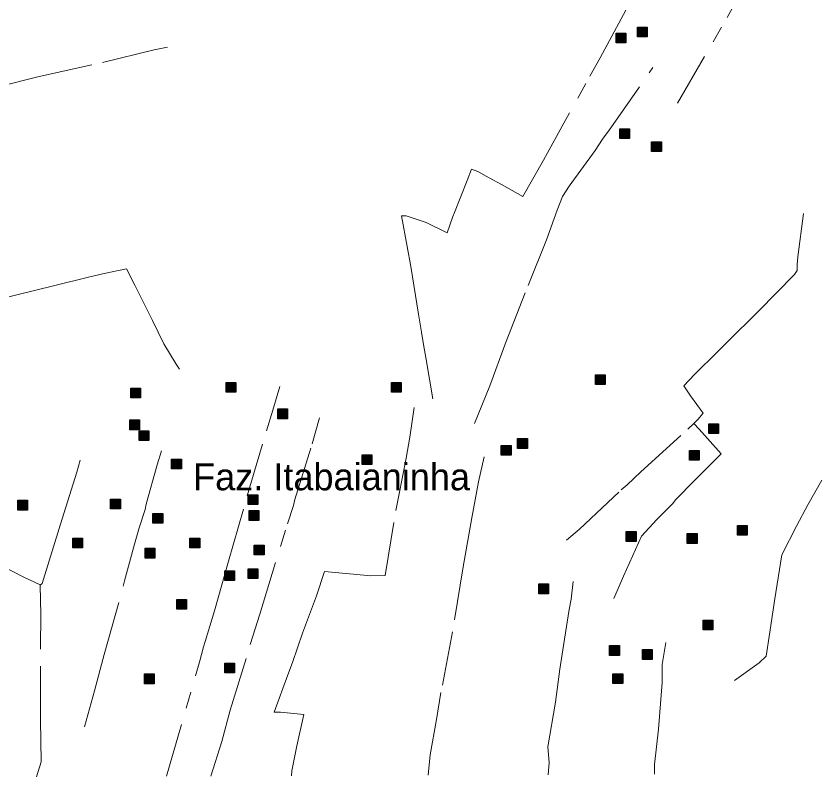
# Model space of a CAD drawing. Extents: x 393.5 to 446.9, y 8064.8 to 8120.4.
# Drawn here: x 413.443 to 418.221, y 8064.925 to 8069.434 of the extents above; entities that cross this region are included whole.
import ezdxf

# ---------------------------------------------------------------- set-up
doc = ezdxf.new("R2010")
doc.units = 0
doc.header["$LTSCALE"] = 0.064
doc.linetypes.add('DOT_DASHED', pattern=[7.7, 5, -1.2, 0.3, -1.2])
doc.layers.add('2', color=7, linetype='Continuous', lineweight=25)
doc.layers.add('22', color=7, linetype='DOT_DASHED', lineweight=13)
doc.layers.add('61', color=7, linetype='Continuous')

msp = doc.modelspace()

# ---------------------------------------------------------------- hatches: boundary and pattern name
at = {"layer": '2'}
for points in [[(417.1265, 8069.3684), (417.1845, 8069.3684), (417.1845, 8069.3104), (417.1265, 8069.3104)], [(417.0004, 8069.3332), (417.0584, 8069.3332), (417.0584, 8069.2752), (417.0004, 8069.2752)], [(417.0219, 8068.7657), (417.0799, 8068.7657), (417.0799, 8068.7077), (417.0219, 8068.7077)], [(417.2112, 8068.689), (417.2692, 8068.689), (417.2692, 8068.631), (417.2112, 8068.631)], [(416.8775, 8067.3086), (416.9355, 8067.3086), (416.9355, 8067.2506), (416.8775, 8067.2506)], [(414.688, 8067.2634), (414.746, 8067.2634), (414.746, 8067.2054), (414.688, 8067.2054)], [(415.6682, 8067.2634), (415.7262, 8067.2634), (415.7262, 8067.2054), (415.6682, 8067.2054)], [(414.1226, 8067.229), (414.1806, 8067.229), (414.1806, 8067.171), (414.1226, 8067.171)], [(414.9945, 8067.1054), (415.0525, 8067.1054), (415.0525, 8067.0474), (414.9945, 8067.0474)], [(414.1167, 8067.0407), (414.1747, 8067.0407), (414.1747, 8066.9827), (414.1167, 8066.9827)], [(417.5499, 8067.0181), (417.6079, 8067.0181), (417.6079, 8066.9601), (417.5499, 8066.9601)], [(414.173, 8066.9761), (414.231, 8066.9761), (414.231, 8066.9181), (414.173, 8066.9181)], [(416.4165, 8066.9296), (416.4745, 8066.9296), (416.4745, 8066.8716), (416.4165, 8066.8716)], [(416.3201, 8066.8889), (416.3781, 8066.8889), (416.3781, 8066.8309), (416.3201, 8066.8309)], [(417.4348, 8066.8598), (417.4928, 8066.8598), (417.4928, 8066.8018), (417.4348, 8066.8018)], [(415.4943, 8066.8342), (415.5523, 8066.8342), (415.5523, 8066.7762), (415.4943, 8066.7762)], [(414.3649, 8066.8086), (414.4229, 8066.8086), (414.4229, 8066.7506), (414.3649, 8066.7506)], [(414.0032, 8066.5708), (414.0612, 8066.5708), (414.0612, 8066.5128), (414.0032, 8066.5128)], [(414.8188, 8066.5967), (414.8768, 8066.5967), (414.8768, 8066.5387), (414.8188, 8066.5387)], [(413.4528, 8066.5648), (413.5108, 8066.5648), (413.5108, 8066.5068), (413.4528, 8066.5068)], [(414.2547, 8066.4869), (414.3127, 8066.4869), (414.3127, 8066.4289), (414.2547, 8066.4289)], [(414.8249, 8066.5031), (414.8829, 8066.5031), (414.8829, 8066.4451), (414.8249, 8066.4451)], [(417.0611, 8066.3789), (417.1191, 8066.3789), (417.1191, 8066.3209), (417.0611, 8066.3209)], [(417.7198, 8066.4158), (417.7778, 8066.4158), (417.7778, 8066.3578), (417.7198, 8066.3578)], [(413.7796, 8066.3397), (413.8376, 8066.3397), (413.8376, 8066.2817), (413.7796, 8066.2817)], [(414.4736, 8066.34), (414.5316, 8066.34), (414.5316, 8066.282), (414.4736, 8066.282)], [(417.4227, 8066.3671), (417.4807, 8066.3671), (417.4807, 8066.3091), (417.4227, 8066.3091)], [(414.8553, 8066.2988), (414.9133, 8066.2988), (414.9133, 8066.2408), (414.8553, 8066.2408)], [(414.2079, 8066.2797), (414.2659, 8066.2797), (414.2659, 8066.2217), (414.2079, 8066.2217)], [(414.6799, 8066.1467), (414.7379, 8066.1467), (414.7379, 8066.0887), (414.6799, 8066.0887)], [(414.8191, 8066.159), (414.8771, 8066.159), (414.8771, 8066.101), (414.8191, 8066.101)], [(416.5422, 8066.0685), (416.6002, 8066.0685), (416.6002, 8066.0105), (416.5422, 8066.0105)], [(414.3957, 8065.9764), (414.4537, 8065.9764), (414.4537, 8065.9184), (414.3957, 8065.9184)], [(417.5171, 8065.8543), (417.5751, 8065.8543), (417.5751, 8065.7963), (417.5171, 8065.7963)], [(416.9624, 8065.7034), (417.0204, 8065.7034), (417.0204, 8065.6454), (416.9624, 8065.6454)], [(417.1562, 8065.6792), (417.2142, 8065.6792), (417.2142, 8065.6212), (417.1562, 8065.6212)], [(414.6803, 8065.5992), (414.7383, 8065.5992), (414.7383, 8065.5412), (414.6803, 8065.5412)], [(414.2039, 8065.535), (414.2619, 8065.535), (414.2619, 8065.477), (414.2039, 8065.477)], [(416.9816, 8065.5358), (417.0396, 8065.5358), (417.0396, 8065.4778), (416.9816, 8065.4778)]]:
    msp.add_hatch(color=256, dxfattribs=at).paths.add_polyline_path(points)

# ---------------------------------------------------------------- linework, layer by layer
for points in [[(417.1265, 8069.3684), (417.1845, 8069.3684), (417.1845, 8069.3104), (417.1265, 8069.3104)], [(417.0004, 8069.3332), (417.0584, 8069.3332), (417.0584, 8069.2752), (417.0004, 8069.2752)], [(417.0219, 8068.7657), (417.0799, 8068.7657), (417.0799, 8068.7077), (417.0219, 8068.7077)], [(417.2112, 8068.689), (417.2692, 8068.689), (417.2692, 8068.631), (417.2112, 8068.631)], [(416.8775, 8067.3086), (416.9355, 8067.3086), (416.9355, 8067.2506), (416.8775, 8067.2506)], [(414.688, 8067.2634), (414.746, 8067.2634), (414.746, 8067.2054), (414.688, 8067.2054)], [(415.6682, 8067.2634), (415.7262, 8067.2634), (415.7262, 8067.2054), (415.6682, 8067.2054)], [(414.1226, 8067.229), (414.1806, 8067.229), (414.1806, 8067.171), (414.1226, 8067.171)], [(414.9945, 8067.1054), (415.0525, 8067.1054), (415.0525, 8067.0474), (414.9945, 8067.0474)], [(414.1167, 8067.0407), (414.1747, 8067.0407), (414.1747, 8066.9827), (414.1167, 8066.9827)], [(417.5499, 8067.0181), (417.6079, 8067.0181), (417.6079, 8066.9601), (417.5499, 8066.9601)], [(414.173, 8066.9761), (414.231, 8066.9761), (414.231, 8066.9181), (414.173, 8066.9181)], [(416.4165, 8066.9296), (416.4745, 8066.9296), (416.4745, 8066.8716), (416.4165, 8066.8716)], [(416.3201, 8066.8889), (416.3781, 8066.8889), (416.3781, 8066.8309), (416.3201, 8066.8309)], [(417.4348, 8066.8598), (417.4928, 8066.8598), (417.4928, 8066.8018), (417.4348, 8066.8018)], [(415.4943, 8066.8342), (415.5523, 8066.8342), (415.5523, 8066.7762), (415.4943, 8066.7762)], [(414.3649, 8066.8086), (414.4229, 8066.8086), (414.4229, 8066.7506), (414.3649, 8066.7506)], [(414.0032, 8066.5708), (414.0612, 8066.5708), (414.0612, 8066.5128), (414.0032, 8066.5128)], [(414.8188, 8066.5967), (414.8768, 8066.5967), (414.8768, 8066.5387), (414.8188, 8066.5387)], [(413.4528, 8066.5648), (413.5108, 8066.5648), (413.5108, 8066.5068), (413.4528, 8066.5068)], [(414.2547, 8066.4869), (414.3127, 8066.4869), (414.3127, 8066.4289), (414.2547, 8066.4289)], [(414.8249, 8066.5031), (414.8829, 8066.5031), (414.8829, 8066.4451), (414.8249, 8066.4451)], [(417.0611, 8066.3789), (417.1191, 8066.3789), (417.1191, 8066.3209), (417.0611, 8066.3209)], [(417.7198, 8066.4158), (417.7778, 8066.4158), (417.7778, 8066.3578), (417.7198, 8066.3578)], [(413.7796, 8066.3397), (413.8376, 8066.3397), (413.8376, 8066.2817), (413.7796, 8066.2817)], [(414.4736, 8066.34), (414.5316, 8066.34), (414.5316, 8066.282), (414.4736, 8066.282)], [(417.4227, 8066.3671), (417.4807, 8066.3671), (417.4807, 8066.3091), (417.4227, 8066.3091)], [(414.8553, 8066.2988), (414.9133, 8066.2988), (414.9133, 8066.2408), (414.8553, 8066.2408)], [(414.2079, 8066.2797), (414.2659, 8066.2797), (414.2659, 8066.2217), (414.2079, 8066.2217)], [(414.6799, 8066.1467), (414.7379, 8066.1467), (414.7379, 8066.0887), (414.6799, 8066.0887)], [(414.8191, 8066.159), (414.8771, 8066.159), (414.8771, 8066.101), (414.8191, 8066.101)], [(416.5422, 8066.0685), (416.6002, 8066.0685), (416.6002, 8066.0105), (416.5422, 8066.0105)], [(414.3957, 8065.9764), (414.4537, 8065.9764), (414.4537, 8065.9184), (414.3957, 8065.9184)], [(417.5171, 8065.8543), (417.5751, 8065.8543), (417.5751, 8065.7963), (417.5171, 8065.7963)], [(416.9624, 8065.7034), (417.0204, 8065.7034), (417.0204, 8065.6454), (416.9624, 8065.6454)], [(417.1562, 8065.6792), (417.2142, 8065.6792), (417.2142, 8065.6212), (417.1562, 8065.6212)], [(414.6803, 8065.5992), (414.7383, 8065.5992), (414.7383, 8065.5412), (414.6803, 8065.5412)], [(414.2039, 8065.535), (414.2619, 8065.535), (414.2619, 8065.477), (414.2039, 8065.477)], [(416.9816, 8065.5358), (417.0396, 8065.5358), (417.0396, 8065.4778), (416.9816, 8065.4778)]]:
    msp.add_lwpolyline(points, close=True, dxfattribs=at)
at = {"layer": '22'}
msp.add_line((413.5866, 8066.0621), (413.586, 8066.0624), dxfattribs=at)
for points in [[(416.3205, 8068.4365), (416.4474, 8068.3655), (416.5706, 8068.5796), (416.8448, 8069.0771), (416.9065, 8069.1873), (417.0942, 8069.5336), (417.1147, 8069.571), (417.1305, 8069.5899)], [(417.3653, 8068.9177), (417.6589, 8069.4259), (417.6985, 8069.4962), (417.7, 8069.4988)], [(412.4913, 8068.8155), (412.6773, 8068.8613), (412.8028, 8068.8883), (412.9867, 8068.934), (413.2711, 8068.9984), (413.5805, 8069.0753), (413.9559, 8069.1589), (414.2612, 8069.2336), (414.3406, 8069.2502)], [(416.9481, 8068.7428), (416.9549, 8068.7526), (417.2182, 8069.1284)], [(416.1609, 8067.019), (416.2529, 8067.2418), (416.345, 8067.4952), (416.4799, 8067.8378), (416.5885, 8068.1084), (416.6518, 8068.284), (416.6827, 8068.3647), (416.7223, 8068.4251), (416.8766, 8068.6377), (416.9204, 8068.7044), (416.9481, 8068.7428)], [(416.0424, 8068.27), (416.1177, 8068.4604), (416.1441, 8068.5269), (416.1815, 8068.512), (416.2488, 8068.4746), (416.3205, 8068.4365)], [(415.7621, 8068.0687), (415.7276, 8068.2497), (415.7557, 8068.2497), (415.8735, 8068.2104), (415.9988, 8068.1488), (416.0324, 8068.2459), (416.0424, 8068.27)], [(418.0736, 8067.9624), (418.079, 8068.0077), (418.1109, 8068.2648)], [(415.8476, 8067.5613), (415.8296, 8067.6676), (415.7837, 8067.9507), (415.7621, 8068.0687)], [(417.4612, 8067.019), (417.4855, 8067.044), (417.5159, 8067.0807), (417.4424, 8067.1829), (417.4024, 8067.2419), (417.4647, 8067.3106), (417.602, 8067.4438), (417.658, 8067.4997), (417.8449, 8067.6848), (418.0589, 8067.9032), (418.0736, 8067.9262), (418.0736, 8067.9451), (418.0736, 8067.9624)], [(414.4117, 8067.3405), (414.3916, 8067.3716), (414.3182, 8067.4925), (414.252, 8067.6303), (414.1464, 8067.8398), (414.0977, 8067.9358), (413.9652, 8067.9088), (413.8716, 8067.8862)], [(413.8716, 8067.8862), (413.6733, 8067.8377), (413.4388, 8067.7794), (412.9923, 8067.6724), (412.9237, 8067.6565), (412.922, 8067.6561)], [(415.9145, 8067.1655), (415.8753, 8067.3991), (415.8584, 8067.4869), (415.8476, 8067.5613)], [(414.5648, 8065.7271), (414.6191, 8065.9096), (414.702, 8066.2036), (414.8135, 8066.5905), (414.9279, 8066.9765), (414.9661, 8067.098), (415.0065, 8067.2381)], [(415.7567, 8066.8142), (415.777, 8066.9379), (415.803, 8067.1142)], [(415.0961, 8066.5683), (415.1992, 8066.8988), (415.2428, 8067.0533)], [(417.0668, 8066.6562), (417.1468, 8066.734), (417.4262, 8066.9855), (417.4612, 8067.019)], [(417.3553, 8066.5698), (417.4648, 8066.6807), (417.6226, 8066.8402), (417.4932, 8066.9854), (417.4614, 8067.0188), (417.4612, 8067.019)], [(414.2149, 8066.542), (414.2791, 8066.7745), (414.3049, 8066.8581)], [(415.0816, 8065.6031), (415.1417, 8065.7774), (415.2246, 8065.9975), (415.2718, 8066.1427), (415.5457, 8066.1158), (415.631, 8066.1181), (415.6954, 8066.5043), (415.7117, 8066.5935), (415.7567, 8066.8142)], [(416.2176, 8066.8223), (416.1844, 8066.6742), (416.1455, 8066.4612), (416.0935, 8066.171), (416.0305, 8065.7841), (415.962, 8065.4247), (415.9361, 8065.2653), (415.8976, 8065.0554), (415.8855, 8064.935)], [(413.8237, 8066.802), (413.8026, 8066.7316), (413.7165, 8066.4542), (413.6461, 8066.2309), (413.597, 8066.0722), (413.5866, 8066.0621)], [(417.7031, 8065.4971), (417.8491, 8065.6007), (417.8896, 8065.6413), (417.9119, 8065.7834), (417.9404, 8065.9682), (417.9834, 8066.2417), (418.0727, 8066.4142), (418.1376, 8066.5382), (418.2207, 8066.6827)], [(416.7068, 8066.328), (416.7831, 8066.3935), (417.0305, 8066.627), (417.0668, 8066.6562)], [(413.8487, 8065.2209), (413.9078, 8065.435), (413.9662, 8065.6506), (414.0867, 8066.0874), (414.1442, 8066.3041), (414.1724, 8066.4003), (414.2079, 8066.5098), (414.2149, 8066.542)], [(414.5968, 8064.9297), (414.6635, 8065.1349), (414.7128, 8065.3215), (414.8314, 8065.7096), (414.8874, 8065.8893), (415.0519, 8066.4248), (415.0877, 8066.5344), (415.0961, 8066.5683)], [(416.9872, 8065.9832), (417.0453, 8066.1148), (417.1504, 8066.3514), (417.243, 8066.4504), (417.3341, 8066.543), (417.3553, 8066.5698)], [(413.586, 8066.0624), (413.4894, 8066.108), (413.3441, 8066.1815), (413.3249, 8066.2037), (413.2597, 8066.3487), (413.2265, 8066.4217), (413.1904, 8066.4942), (413.183, 8066.512)], [(413.5901, 8065.8634), (413.5901, 8065.886), (413.5866, 8066.0606), (413.5866, 8066.0621)], [(416.7453, 8066.083), (416.7343, 8065.9776), (416.7214, 8065.9167), (416.6955, 8065.7422), (416.6679, 8065.5637), (416.6421, 8065.3678), (416.5953, 8065.1042), (416.6034, 8065.0109), (416.5973, 8064.938)], [(413.5645, 8064.9253), (413.5909, 8065.0148), (413.5872, 8065.2618), (413.5881, 8065.7154), (413.5901, 8065.8634)], [(414.3345, 8064.9286), (414.532, 8065.6121), (414.5416, 8065.6503), (414.5545, 8065.6967), (414.5648, 8065.7271)], [(417.2279, 8064.9406), (417.2279, 8064.9987), (417.2522, 8065.2083), (417.2746, 8065.4848), (417.2746, 8065.5903), (417.2949, 8065.7221)], [(415.0756, 8064.9317), (415.078, 8064.9617), (415.1067, 8065.1094), (415.1501, 8065.2942), (415.0101, 8065.3084), (414.9736, 8065.3084), (415.0547, 8065.5295), (415.0816, 8065.6031)]]:
    msp.add_lwpolyline(points, dxfattribs=at)

# ---------------------------------------------------------------- texts
at = {"layer": '61'}
msp.add_text('Faz. Itabaianinha', height=0.16, dxfattribs=at).set_placement((414.4928, 8066.6236))

doc.saveas('drawing.dxf')
